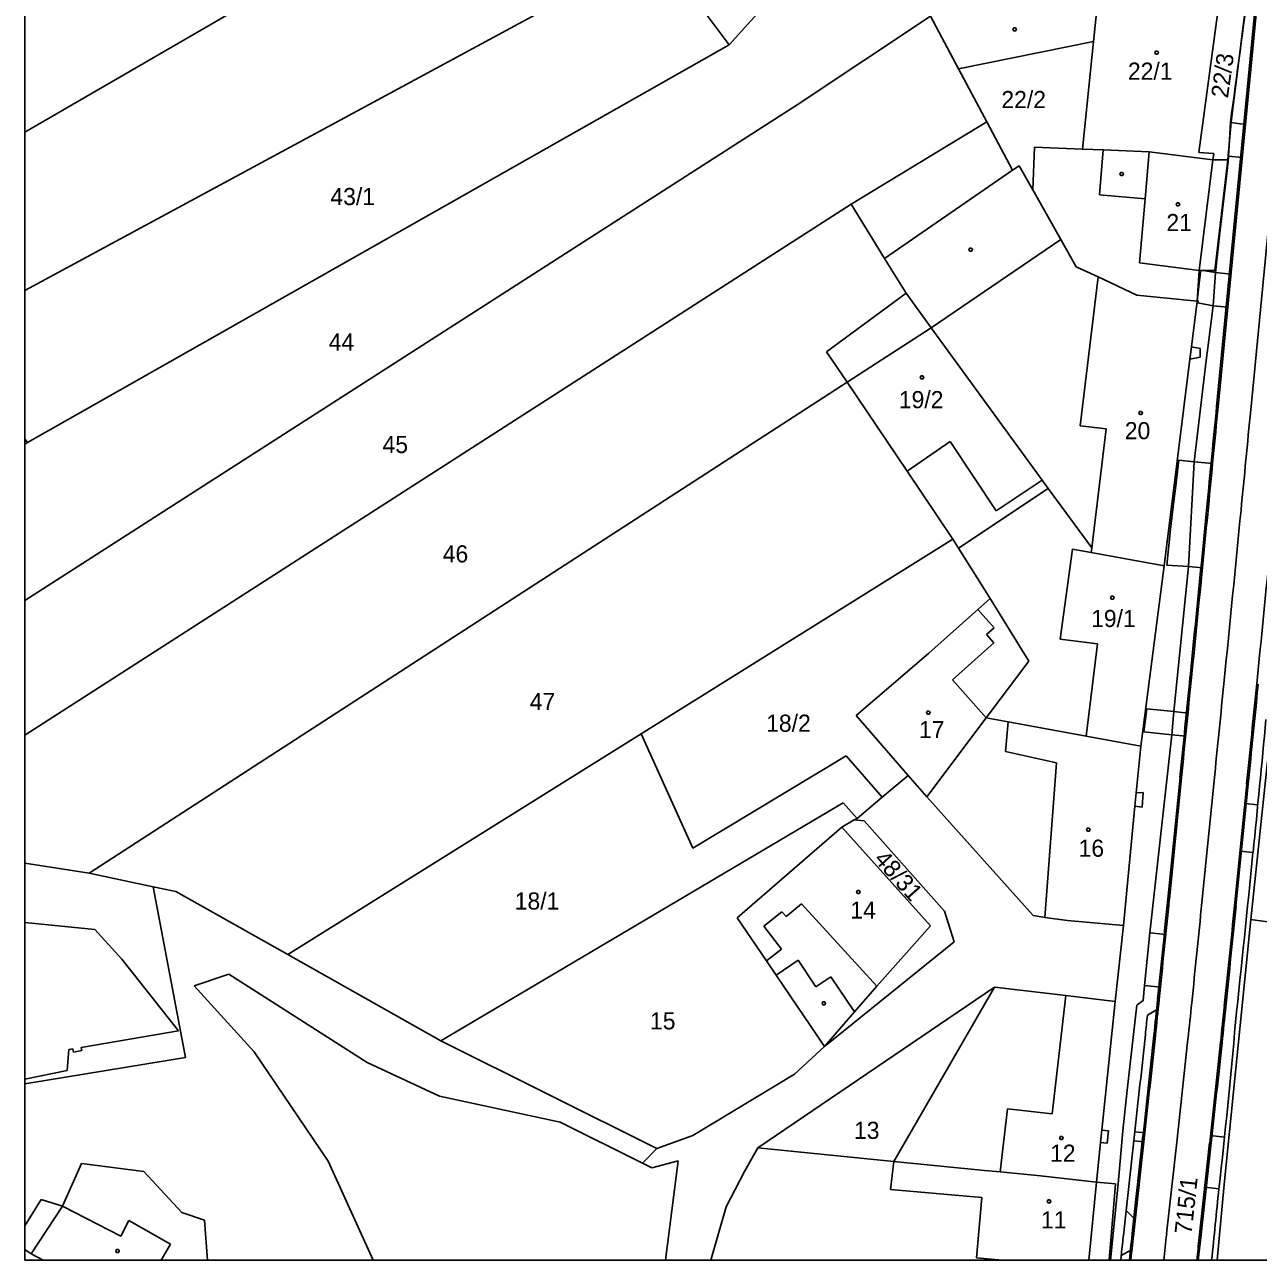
# Model space of a CAD drawing. Extents: x -639621 to -639329, y -1192893 to -1192488.
# Drawn here: x -639621.3 to -639498.9, y -1192893.3 to -1192770.8 of the extents above; entities that cross this region are included whole.
import ezdxf

# ---------------------------------------------------------------- set-up
doc = ezdxf.new("R2010")
doc.units = 0
for name, color, linetype in [('Vrstva 1', 7, 'Continuous'), ('Vrstva 19', 7, 'Continuous'), ('Vrstva 2', 7, 'Continuous'), ('Vrstva 20', 7, 'Continuous'), ('Vrstva 4', 7, 'Continuous'), ('Vrstva 5', 7, 'Continuous'), ('Vrstva 61', 7, 'Continuous')]:
    doc.layers.add(name, color=color, linetype=linetype)

msp = doc.modelspace()

# ---------------------------------------------------------------- linework, layer by layer
at = {"layer": 'Vrstva 1'}
for p, q in [((-639567.88, -1192750.5), (-639621.26, -1192781.4)), ((-639558.48, -1192763.2), (-639621.26, -1192797.12)), ((-639551.4, -1192772.76), (-639558.48, -1192763.2)), ((-639543.8, -1192764.31), (-639551.4, -1192772.76)), ((-639504.82, -1192783.44), (-639502.43, -1192765.91)), ((-639501.61, -1192780.38), (-639499.83, -1192766.37)), ((-639531.42, -1192769.91), (-639544.66, -1192778.72)), ((-639528.64, -1192775.13), (-639531.42, -1192769.91)), ((-639551.4, -1192772.76), (-639621, -1192812.21)), ((-639528.64, -1192775.13), (-639515.25, -1192772.42)), ((-639515.25, -1192772.42), (-639516.34, -1192783.09)), ((-639525.84, -1192780.38), (-639528.64, -1192775.13)), ((-639544.66, -1192778.72), (-639621.26, -1192827.88)), ((-639539.3, -1192788.57), (-639525.84, -1192780.38)), ((-639523.27, -1192785.19), (-639525.84, -1192780.38)), ((-639501.94, -1192784.17), (-639501.61, -1192780.38)), ((-639521.11, -1192782.9), (-639521.28, -1192787.13)), ((-639516.34, -1192783.09), (-639521.11, -1192782.9)), ((-639514.3, -1192783.17), (-639516.34, -1192783.09)), ((-639509.72, -1192783.36), (-639514.3, -1192783.17)), ((-639503.4, -1192784.15), (-639509.72, -1192783.36)), ((-639504.82, -1192783.44), (-639503.32, -1192783.54)), ((-639503.4, -1192784.15), (-639503.32, -1192783.54)), ((-639501.94, -1192784.17), (-639503.4, -1192784.15)), ((-639503.23, -1192795.15), (-639501.94, -1192784.17)), ((-639522.63, -1192784.75), (-639523.27, -1192785.19)), ((-639521.28, -1192787.13), (-639522.63, -1192784.75)), ((-639518.5, -1192792.05), (-639521.28, -1192787.13)), ((-639621.26, -1192841.23), (-639539.3, -1192788.57)), ((-639535.98, -1192793.95), (-639539.3, -1192788.57)), ((-639516.97, -1192794.76), (-639518.5, -1192792.05)), ((-639533.84, -1192797.4), (-639535.98, -1192793.95)), ((-639514.78, -1192795.78), (-639516.97, -1192794.76)), ((-639504.98, -1192798.18), (-639504.77, -1192795.13)), ((-639504.77, -1192795.13), (-639503.23, -1192795.15)), ((-639510.94, -1192797.57), (-639514.78, -1192795.78)), ((-639541.72, -1192803.2), (-639533.84, -1192797.4)), ((-639533.84, -1192797.4), (-639531.35, -1192800.82)), ((-639504.98, -1192798.18), (-639510.94, -1192797.57)), ((-639505.54, -1192802.7), (-639504.98, -1192798.18)), ((-639531.35, -1192800.82), (-639520.33, -1192815.94)), ((-639541.72, -1192803.2), (-639539.7, -1192806.21)), ((-639505.7, -1192803.94), (-639504.68, -1192803.75)), ((-639504.68, -1192802.89), (-639505.54, -1192802.7)), ((-639504.68, -1192803.75), (-639504.68, -1192802.89)), ((-639508.25, -1192824.43), (-639505.7, -1192803.94)), ((-639614.88, -1192854.94), (-639539.7, -1192806.21)), ((-639539.7, -1192806.21), (-639533.72, -1192815.06)), ((-639621.26, -1192811.84), (-639621, -1192812.21)), ((-639621, -1192812.21), (-639621.26, -1192812.36)), ((-639533.72, -1192815.06), (-639529.19, -1192821.78)), ((-639520.33, -1192815.94), (-639519.74, -1192816.75)), ((-639528.63, -1192822.67), (-639519.74, -1192816.75)), ((-639519.74, -1192816.75), (-639515.43, -1192822.65)), ((-639529.19, -1192821.78), (-639560.12, -1192841.09)), ((-639528.63, -1192822.67), (-639529.19, -1192821.78)), ((-639525.5, -1192827.68), (-639528.63, -1192822.67)), ((-639515.43, -1192822.65), (-639515.49, -1192823.12)), ((-639508.25, -1192824.43), (-639515.49, -1192823.12)), ((-639510.56, -1192842.33), (-639508.25, -1192824.43)), ((-639526.73, -1192828.78), (-639525.5, -1192827.68)), ((-639525.5, -1192827.68), (-639521.67, -1192833.89)), ((-639531.59, -1192833.11), (-639526.73, -1192828.78)), ((-639538.8, -1192839.27), (-639531.59, -1192833.11)), ((-639525.91, -1192839.52), (-639521.67, -1192833.89)), ((-639533.62, -1192845.24), (-639538.8, -1192839.27)), ((-639531.79, -1192847.35), (-639525.91, -1192839.52)), ((-639525.91, -1192839.52), (-639523.71, -1192839.92)), ((-639523.71, -1192839.92), (-639515.97, -1192841.34)), ((-639560.12, -1192841.09), (-639595.18, -1192863)), ((-639560.12, -1192841.09), (-639554.98, -1192852.45)), ((-639515.97, -1192841.34), (-639510.56, -1192842.33)), ((-639511.01, -1192846.96), (-639510.56, -1192842.33)), ((-639554.98, -1192852.45), (-639539.77, -1192843.3)), ((-639539.77, -1192843.3), (-639536.21, -1192847.4)), ((-639497.98, -1192843.85), (-639499.64, -1192859.54)), ((-639536.21, -1192847.4), (-639533.62, -1192845.24)), ((-639531.79, -1192847.35), (-639533.62, -1192845.24)), ((-639540.09, -1192847.96), (-639580, -1192871.57)), ((-639538.71, -1192849.49), (-639540.09, -1192847.96)), ((-639538.71, -1192849.49), (-639536.21, -1192847.4)), ((-639521.25, -1192859.13), (-639531.79, -1192847.35)), ((-639510.32, -1192846.92), (-639511.01, -1192846.96)), ((-639510.42, -1192848.39), (-639510.32, -1192846.92)), ((-639512.29, -1192860.12), (-639511.14, -1192848.29)), ((-639511.14, -1192848.29), (-639510.42, -1192848.39)), ((-639540.23, -1192850.37), (-639550.59, -1192859.35)), ((-639540.23, -1192850.37), (-639538.98, -1192849.64)), ((-639531.42, -1192860.16), (-639540.23, -1192850.37)), ((-639538.98, -1192849.64), (-639538.71, -1192849.49)), ((-639538.98, -1192849.64), (-639538.01, -1192849.73)), ((-639538.01, -1192849.73), (-639530.02, -1192858.69)), ((-639614.88, -1192854.94), (-639621.26, -1192853.92)), ((-639608.52, -1192856.27), (-639614.88, -1192854.94)), ((-639605.31, -1192873.2), (-639608.52, -1192856.27)), ((-639606.26, -1192856.74), (-639608.52, -1192856.27)), ((-639595.18, -1192863), (-639606.26, -1192856.74)), ((-639530.02, -1192858.69), (-639529.06, -1192861.73)), ((-639621.26, -1192859.82), (-639614.31, -1192860.51)), ((-639547.69, -1192863.63), (-639550.59, -1192859.35)), ((-639531.42, -1192860.16), (-639536.75, -1192866.15)), ((-639520.08, -1192859.32), (-639521.25, -1192859.13)), ((-639517.82, -1192859.63), (-639520.08, -1192859.32)), ((-639512.29, -1192860.12), (-639517.82, -1192859.63)), ((-639512.29, -1192860.12), (-639513.1, -1192867.65)), ((-639499.64, -1192859.54), (-639502.3, -1192885.82)), ((-639460.93, -1192864.78), (-639499.64, -1192859.54)), ((-639614.31, -1192860.51), (-639611.62, -1192863.46)), ((-639529.06, -1192861.73), (-639541.93, -1192872.12)), ((-639611.62, -1192863.46), (-639606, -1192870.58)), ((-639580, -1192871.57), (-639595.18, -1192863)), ((-639546.73, -1192865.04), (-639547.69, -1192863.63)), ((-639604.47, -1192866.09), (-639601, -1192864.96)), ((-639601, -1192864.96), (-639587.31, -1192873.7)), ((-639541.93, -1192872.12), (-639546.73, -1192865.04)), ((-639598.5, -1192872.64), (-639604.47, -1192866.09)), ((-639525.06, -1192866.23), (-639548.56, -1192882.19)), ((-639536.75, -1192866.15), (-639538.95, -1192868.69)), ((-639525.06, -1192866.23), (-639535.07, -1192883.53)), ((-639517.99, -1192867.05), (-639525.06, -1192866.23)), ((-639513.1, -1192867.65), (-639517.99, -1192867.05)), ((-639538.95, -1192868.69), (-639541.93, -1192872.12)), ((-639514.43, -1192880.41), (-639513.1, -1192867.65)), ((-639606, -1192870.58), (-639615.65, -1192872.22)), ((-639616.87, -1192872.43), (-639617.06, -1192874.51)), ((-639616.49, -1192872.37), (-639616.87, -1192872.43)), ((-639616.49, -1192872.37), (-639616.43, -1192872.67)), ((-639615.6, -1192872.53), (-639615.65, -1192872.22)), ((-639580, -1192871.57), (-639558.56, -1192882.23)), ((-639541.93, -1192872.12), (-639544.9, -1192874.86)), ((-639621.26, -1192875.84), (-639605.31, -1192873.2)), ((-639616.43, -1192872.67), (-639615.6, -1192872.53)), ((-639591.17, -1192883.51), (-639598.5, -1192872.64)), ((-639587.31, -1192873.7), (-639580.13, -1192877.06)), ((-639617.06, -1192874.51), (-639621.26, -1192875.37)), ((-639544.9, -1192874.86), (-639555, -1192880.97)), ((-639580.13, -1192877.06), (-639568.16, -1192879.64)), ((-639568.16, -1192879.64), (-639559.97, -1192883.7)), ((-639558.56, -1192882.23), (-639555, -1192880.97)), ((-639513.76, -1192880.48), (-639514.43, -1192880.41)), ((-639513.89, -1192881.71), (-639513.76, -1192880.48)), ((-639559.97, -1192883.7), (-639558.56, -1192882.23)), ((-639548.56, -1192882.19), (-639549.88, -1192884.53)), ((-639535.07, -1192883.53), (-639548.56, -1192882.19)), ((-639514.97, -1192885.59), (-639514.56, -1192881.64)), ((-639514.56, -1192881.64), (-639513.89, -1192881.71)), ((-639559.07, -1192884.15), (-639556.45, -1192883.48)), ((-639556.45, -1192883.48), (-639557.71, -1192893.33)), ((-639617.51, -1192887.95), (-639615.62, -1192883.72)), ((-639615.62, -1192883.72), (-639609.46, -1192884.51)), ((-639609.46, -1192884.51), (-639605.69, -1192888.6)), ((-639586.7, -1192893.33), (-639591.17, -1192883.51)), ((-639559.97, -1192883.7), (-639559.07, -1192884.15)), ((-639551.68, -1192888.03), (-639549.88, -1192884.53)), ((-639526.07, -1192884.42), (-639535.07, -1192883.53)), ((-639524.51, -1192884.57), (-639526.07, -1192884.42)), ((-639520.5, -1192884.97), (-639524.51, -1192884.57)), ((-639514.97, -1192885.59), (-639520.5, -1192884.97)), ((-639513.07, -1192885.76), (-639514.97, -1192885.59)), ((-639513.7, -1192893.33), (-639513.07, -1192885.76)), ((-639502.3, -1192885.82), (-639502.98, -1192893.33)), ((-639621.26, -1192889.92), (-639619.64, -1192887.29)), ((-639619.64, -1192887.29), (-639617.51, -1192887.95)), ((-639553.21, -1192893.33), (-639551.68, -1192888.03)), ((-639605.69, -1192888.6), (-639603.44, -1192889.34)), ((-639603.44, -1192889.34), (-639603.13, -1192893.33)), ((-639620.61, -1192892.68), (-639621.26, -1192892.26)), ((-639619.43, -1192893.33), (-639620.61, -1192892.68))]:
    msp.add_line(p, q, dxfattribs=at)
at = {"layer": 'Vrstva 19'}
for p, q in [((-639498.78, -1192766.2), (-639502.89, -1192808.65)), ((-639506.52, -1192845.44), (-639507.73, -1192857.52)), ((-639500.05, -1192846.09), (-639501.27, -1192858.17)), ((-639510.2, -1192880.97), (-639511.23, -1192890.36)), ((-639503.74, -1192881.68), (-639504.76, -1192891.07))]:
    msp.add_line(p, q, dxfattribs=at)
for points in [[(-639495.55, -1192766.51), (-639499.66, -1192808.96)], [(-639503.29, -1192845.77), (-639504.5, -1192857.84)], [(-639506.97, -1192881.32), (-639508, -1192890.71)]]:
    msp.add_lwpolyline(points, dxfattribs=at)
for centre, radius, start, end in [((-654430.04, -1191365.48), 14996.75, 354.439585, 354.477782), ((-654430.04, -1191365.48), 15000, 354.439585, 354.477782), ((-646965.2, -1192091.38), 7496.7, 354.303419, 354.433219), ((-646965.2, -1192091.38), 7499.95, 354.303419, 354.433219), ((-646965.2, -1192091.38), 7503.2, 354.303419, 354.433219), ((-654422.97, -1191345.77), 14991.64, 354.258866, 354.297057), ((-654428.05, -1191345.26), 15000, 354.258856, 354.297053), ((-654422.97, -1191345.77), 14998.14, 354.258866, 354.297057), ((-642489.65, -1192559.73), 2996.75, 354.10607, 354.29705), ((-642489.65, -1192559.73), 3000, 354.10607, 354.29705), ((-642489.65, -1192559.73), 3003.25, 354.10607, 354.29705), ((-640997.53, -1192712.93), 1496.79, 353.93638, 354.07424), ((-640997.53, -1192712.93), 1500.04, 353.93638, 354.07424), ((-640997.53, -1192712.93), 1503.29, 353.93638, 354.07424), ((-642488.93, -1192552.83), 2996.76, 353.71357, 353.90455), ((-642488.93, -1192552.83), 3000, 353.71357, 353.90455), ((-642488.93, -1192552.83), 3003.26, 353.71357, 353.90455), ((-638527.12, -1192999.08), 990.09, 173.69574, 173.869), ((-638527.12, -1192999.08), 986.84, 173.69574, 173.84873), ((-638527.12, -1192999.08), 983.59, 173.69574, 173.82832)]:
    msp.add_arc(centre, radius, start, end, dxfattribs=at)
at = {"layer": 'Vrstva 20'}
for p, q in [((-639498.93, -1192766.18), (-639503.04, -1192808.63)), ((-639501.67, -1192780.46), (-639501.88, -1192784.36)), ((-639501.67, -1192780.46), (-639500.18, -1192780.64)), ((-639501.85, -1192783.79), (-639500.5, -1192783.92)), ((-639501.88, -1192784.36), (-639502.74, -1192791.71)), ((-639502.74, -1192791.71), (-639503.16, -1192795.34)), ((-639503.16, -1192795.34), (-639503.37, -1192798.63)), ((-639503.16, -1192795.34), (-639501.62, -1192795.49)), ((-639503.37, -1192798.63), (-639503.92, -1192802.8)), ((-639503.37, -1192798.63), (-639501.94, -1192798.77)), ((-639503.92, -1192802.8), (-639504.09, -1192804.08)), ((-639504.09, -1192804.08), (-639505.26, -1192814.12)), ((-639505.26, -1192814.12), (-639505.83, -1192824.5)), ((-639505.26, -1192814.12), (-639503.44, -1192814.3)), ((-639505.83, -1192824.5), (-639504.45, -1192824.64)), ((-639508.26, -1192838.8), (-639507.27, -1192838.9)), ((-639507.27, -1192838.9), (-639505.88, -1192839.04)), ((-639507.49, -1192841.2), (-639506.11, -1192841.33)), ((-639506.67, -1192845.43), (-639507.88, -1192857.5)), ((-639499.9, -1192846.11), (-639501.12, -1192858.18)), ((-639498.96, -1192848.16), (-639500.25, -1192848.03)), ((-639499.43, -1192852.89), (-639500.72, -1192852.76)), ((-639509.65, -1192860.86), (-639508.09, -1192861.02)), ((-639510.19, -1192866.08), (-639508.62, -1192866.24)), ((-639509.91, -1192869.03), (-639508.84, -1192868.38)), ((-639511.19, -1192880.86), (-639512.22, -1192890.25)), ((-639510.35, -1192880.95), (-639511.37, -1192890.34)), ((-639511.16, -1192880.58), (-639510.17, -1192880.69)), ((-639502.26, -1192881.12), (-639503.66, -1192880.97)), ((-639511.26, -1192881.47), (-639510.26, -1192881.57)), ((-639503.59, -1192881.69), (-639504.62, -1192891.08)), ((-639502.82, -1192886.24), (-639504.22, -1192886.09)), ((-639512.02, -1192888.41), (-639511.11, -1192889.29)), ((-639512.5, -1192892.85), (-639511.43, -1192892.26))]:
    msp.add_line(p, q, dxfattribs=at)
for points in [[(-639503.37, -1192798.63), (-639504.9, -1192798.34), (-639504.87, -1192798.16), (-639504.97, -1192798.15), (-639504.63, -1192795.27), (-639504.62, -1192795.12), (-639503.16, -1192795.34)], [(-639507.99, -1192824.38), (-639505.83, -1192824.5), (-639505.26, -1192814.12), (-639506.8, -1192813.97), (-639507.12, -1192816.76), (-639507.28, -1192818.03), (-639507.61, -1192820.81)]]:
    msp.add_lwpolyline(points, close=True, dxfattribs=at)
for points in [[(-639505.83, -1192824.5), (-639507.27, -1192838.9), (-639507.49, -1192841.2), (-639509.65, -1192860.86), (-639510.19, -1192866.08), (-639510.33, -1192867.57), (-639510.97, -1192868.03), (-639511.91, -1192876.46), (-639512.33, -1192880.5), (-639512.79, -1192885.74)], [(-639508.26, -1192838.8), (-639509.95, -1192838.63), (-639510.25, -1192840.92), (-639507.49, -1192841.2)], [(-639512.79, -1192885.74), (-639513.56, -1192893.33)]]:
    msp.add_lwpolyline(points, dxfattribs=at)
for centre, radius, start, end in [((-637019, -1193111.1), 2504.59, 172.08826, 172.41402), ((-654430.04, -1191365.48), 14996.6, 354.439585, 354.477782), ((-646965.2, -1192091.38), 7496.55, 354.303419, 354.433219), ((-654422.97, -1191345.77), 14991.49, 354.258866, 354.297057), ((-654422.97, -1191345.77), 14998.29, 354.258866, 354.297057), ((-641337.4, -1192667.87), 1847.26, 354.25167, 354.66271), ((-641310.47, -1192674.16), 1819.83, 353.83099, 354.3637), ((-642489.65, -1192559.73), 2996.6, 354.10607, 354.29705), ((-642489.65, -1192559.73), 3003.4, 354.10607, 354.29705), ((-640997.53, -1192712.93), 1496.64, 353.93638, 354.07424), ((-640997.53, -1192712.93), 1503.44, 353.93638, 354.07424), ((-640997.53, -1192712.93), 1495.79, 353.93638, 354.0097), ((-640075.66, -1192820.68), 576.58, 353.47136, 355.12119), ((-642488.93, -1192552.83), 2995.76, 353.71357, 353.90455), ((-642488.93, -1192552.83), 2996.61, 353.71357, 353.90455), ((-642488.93, -1192552.83), 3003.41, 353.71357, 353.90455), ((-642380.95, -1192599.8), 2892.35, 354.17526, 354.31649), ((-638527.12, -1192999.08), 991.09, 173.69574, 173.87521), ((-638527.12, -1192999.08), 990.24, 173.69574, 173.86993), ((-638527.12, -1192999.08), 983.44, 173.69574, 173.82738)]:
    msp.add_arc(centre, radius, start, end, dxfattribs=at)
at = {"layer": 'Vrstva 4'}
for p, q in [((-639514.66, -1192766.67), (-639515.25, -1192772.42)), ((-639514.3, -1192783.17), (-639514.67, -1192787.64)), ((-639510.13, -1192788.03), (-639509.72, -1192783.36)), ((-639504.77, -1192795.13), (-639503.4, -1192784.15)), ((-639523.27, -1192785.19), (-639535.98, -1192793.95)), ((-639514.67, -1192787.64), (-639510.13, -1192788.03)), ((-639510.13, -1192788.03), (-639510.69, -1192794.39)), ((-639531.35, -1192800.82), (-639518.5, -1192792.05)), ((-639510.69, -1192794.39), (-639504.77, -1192795.13)), ((-639514.78, -1192795.78), (-639516.58, -1192810.54)), ((-639539.7, -1192806.21), (-639531.35, -1192800.82)), ((-639505.7, -1192803.94), (-639505.54, -1192802.7)), ((-639514, -1192810.86), (-639516.58, -1192810.54)), ((-639515.43, -1192822.65), (-639514, -1192810.86)), ((-639533.72, -1192815.06), (-639529.47, -1192812.12)), ((-639524.92, -1192818.97), (-639529.47, -1192812.12)), ((-639520.33, -1192815.94), (-639524.92, -1192818.97)), ((-639517.33, -1192822.78), (-639518.57, -1192831.73)), ((-639515.49, -1192823.12), (-639517.33, -1192822.78)), ((-639526.73, -1192828.78), (-639525.12, -1192830.59)), ((-639525.12, -1192830.59), (-639525.87, -1192831.25)), ((-639525.87, -1192831.25), (-639525.13, -1192832.09)), ((-639518.57, -1192831.73), (-639514.87, -1192832.18)), ((-639525.13, -1192832.09), (-639529.25, -1192835.75)), ((-639515.97, -1192841.34), (-639514.87, -1192832.18)), ((-639525.91, -1192839.52), (-639529.25, -1192835.75)), ((-639523.71, -1192839.92), (-639523.99, -1192842.86)), ((-639518.91, -1192843.98), (-639523.99, -1192842.86)), ((-639520.08, -1192859.32), (-639518.91, -1192843.98)), ((-639511.01, -1192846.96), (-639511.14, -1192848.29)), ((-639547.96, -1192860.18), (-639546.15, -1192858.77)), ((-639546.15, -1192858.77), (-639545.73, -1192859.23)), ((-639545.73, -1192859.23), (-639544.2, -1192857.96)), ((-639536.75, -1192866.15), (-639544.2, -1192857.96)), ((-639546.19, -1192862.47), (-639547.96, -1192860.18)), ((-639547.69, -1192863.63), (-639546.19, -1192862.47)), ((-639544.56, -1192863.57), (-639546.73, -1192865.04)), ((-639542.78, -1192866.2), (-639544.56, -1192863.57)), ((-639541.32, -1192865.21), (-639542.78, -1192866.2)), ((-639538.95, -1192868.69), (-639541.32, -1192865.21)), ((-639517.99, -1192867.05), (-639519.35, -1192878.82)), ((-639524.51, -1192884.57), (-639523.78, -1192878.31)), ((-639523.78, -1192878.31), (-639519.35, -1192878.82)), ((-639514.56, -1192881.64), (-639514.43, -1192880.41)), ((-639535.07, -1192883.53), (-639535.39, -1192886.3)), ((-639514.97, -1192885.59), (-639515.73, -1192893.33)), ((-639535.39, -1192886.3), (-639526.32, -1192887.09)), ((-639526.32, -1192887.09), (-639526.87, -1192893.1)), ((-639617.51, -1192887.95), (-639620.61, -1192892.68)), ((-639617.51, -1192887.95), (-639611.74, -1192890.94)), ((-639611.74, -1192890.94), (-639610.92, -1192889.4)), ((-639610.92, -1192889.4), (-639606.79, -1192891.74)), ((-639607.74, -1192893.33), (-639606.79, -1192891.74)), ((-639526.87, -1192893.1), (-639524.3, -1192893.33))]:
    msp.add_line(p, q, dxfattribs=at)
at = {"layer": 'Vrstva 5'}
for points in [[(-639522.98, -1192771.07), (-639522.89, -1192771.22), (-639522.98, -1192771.37), (-639523.16, -1192771.37), (-639523.25, -1192771.22), (-639523.16, -1192771.07)], [(-639508.91, -1192773.37), (-639508.82, -1192773.52), (-639508.91, -1192773.67), (-639509.09, -1192773.67), (-639509.18, -1192773.52), (-639509.09, -1192773.37)], [(-639512.37, -1192785.41), (-639512.28, -1192785.56), (-639512.37, -1192785.71), (-639512.55, -1192785.71), (-639512.64, -1192785.56), (-639512.55, -1192785.41)], [(-639506.79, -1192788.43), (-639506.7, -1192788.58), (-639506.79, -1192788.73), (-639506.97, -1192788.73), (-639507.06, -1192788.58), (-639506.97, -1192788.43)], [(-639527.34, -1192792.92), (-639527.25, -1192793.07), (-639527.34, -1192793.22), (-639527.52, -1192793.22), (-639527.61, -1192793.07), (-639527.52, -1192792.92)], [(-639532.18, -1192805.6), (-639532.09, -1192805.75), (-639532.18, -1192805.9), (-639532.36, -1192805.9), (-639532.45, -1192805.75), (-639532.36, -1192805.6)], [(-639510.48, -1192809.12), (-639510.39, -1192809.27), (-639510.48, -1192809.42), (-639510.66, -1192809.42), (-639510.75, -1192809.27), (-639510.66, -1192809.12)], [(-639513.29, -1192827.46), (-639513.2, -1192827.61), (-639513.29, -1192827.76), (-639513.47, -1192827.76), (-639513.56, -1192827.61), (-639513.47, -1192827.46)], [(-639531.55, -1192838.84), (-639531.46, -1192838.99), (-639531.55, -1192839.14), (-639531.73, -1192839.14), (-639531.82, -1192838.99), (-639531.73, -1192838.84)], [(-639515.68, -1192850.45), (-639515.59, -1192850.6), (-639515.68, -1192850.75), (-639515.86, -1192850.75), (-639515.95, -1192850.6), (-639515.86, -1192850.45)], [(-639538.48, -1192856.64), (-639538.39, -1192856.79), (-639538.48, -1192856.94), (-639538.66, -1192856.94), (-639538.75, -1192856.79), (-639538.66, -1192856.64)], [(-639541.91, -1192867.68), (-639541.82, -1192867.83), (-639541.91, -1192867.98), (-639542.09, -1192867.98), (-639542.18, -1192867.83), (-639542.09, -1192867.68)], [(-639518.35, -1192881.04), (-639518.26, -1192881.19), (-639518.35, -1192881.34), (-639518.53, -1192881.34), (-639518.62, -1192881.19), (-639518.53, -1192881.04)], [(-639519.57, -1192887.35), (-639519.48, -1192887.5), (-639519.57, -1192887.65), (-639519.75, -1192887.65), (-639519.84, -1192887.5), (-639519.75, -1192887.35)], [(-639611.97, -1192892.25), (-639611.88, -1192892.4), (-639611.97, -1192892.55), (-639612.15, -1192892.55), (-639612.24, -1192892.4), (-639612.15, -1192892.25)]]:
    msp.add_lwpolyline(points, close=True, dxfattribs=at)
at = {"layer": 'Vrstva 61'}
for points in [[(-639621.26, -1192893.33), (-639621.26, -1192487.83)], [(-639329.26, -1192893.33), (-639621.26, -1192893.33)]]:
    msp.add_lwpolyline(points, dxfattribs=at)

# ---------------------------------------------------------------- texts
at = {"layer": 'Vrstva 2'}
for s, rotation, p in [('22/3', 82.1049, (-639501.92, -1192778.1)), ('48/31', 311.6317, (-639537.11, -1192853.6)), ('715/1', 83.7882, (-639505.53, -1192890.81))]:
    msp.add_text(s, height=1.7, rotation=rotation, dxfattribs=at).set_placement(p)
for s, p in [('22/1', (-639511.84, -1192776.21)), ('22/2', (-639524.39, -1192779.03)), ('43/1', (-639590.94, -1192788.65)), ('21', (-639508.02, -1192791.23)), ('44', (-639591.11, -1192803.08)), ('19/2', (-639534.56, -1192808.8)), ('20', (-639512.15, -1192811.88)), ('45', (-639585.77, -1192813.25)), ('46', (-639579.8, -1192824.1)), ('19/1', (-639515.49, -1192830.51)), ('47', (-639571.17, -1192838.75)), ('18/2', (-639547.72, -1192840.9)), ('17', (-639532.56, -1192841.53)), ('16', (-639516.73, -1192853.3)), ('18/1', (-639572.66, -1192858.54)), ('14', (-639539.37, -1192859.44)), ('15', (-639559.24, -1192870.43)), ('13', (-639539.01, -1192881.29)), ('12', (-639519.56, -1192883.56)), ('11', (-639520.46, -1192890.17))]:
    msp.add_text(s, height=1.7, dxfattribs=at).set_placement(p)

doc.saveas('drawing.dxf')
